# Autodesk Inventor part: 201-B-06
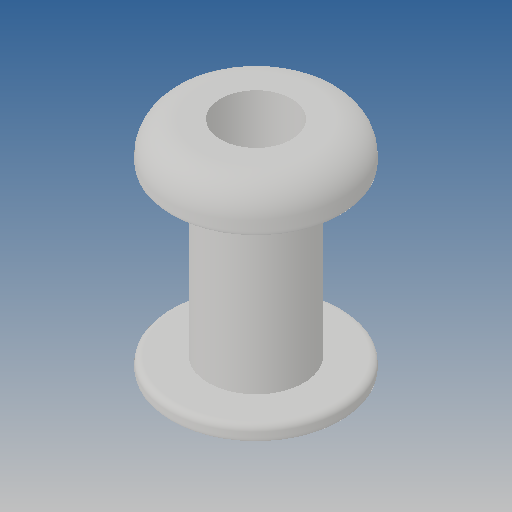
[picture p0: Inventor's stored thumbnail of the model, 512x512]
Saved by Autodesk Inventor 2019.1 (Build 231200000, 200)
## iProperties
Created: 2012-01
Part Number: 201-B-06
Material: Ogólny
Document SubType Name: Modeling
Designer: CADENGINEERING4
Density: 1 g/cm^3
Appearance: Domyślna
Author: CADENGINEERING4
Revision Number: ÈÎºÎ
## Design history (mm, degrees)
feature "Ðý×ª1"
node "Bryła1"
